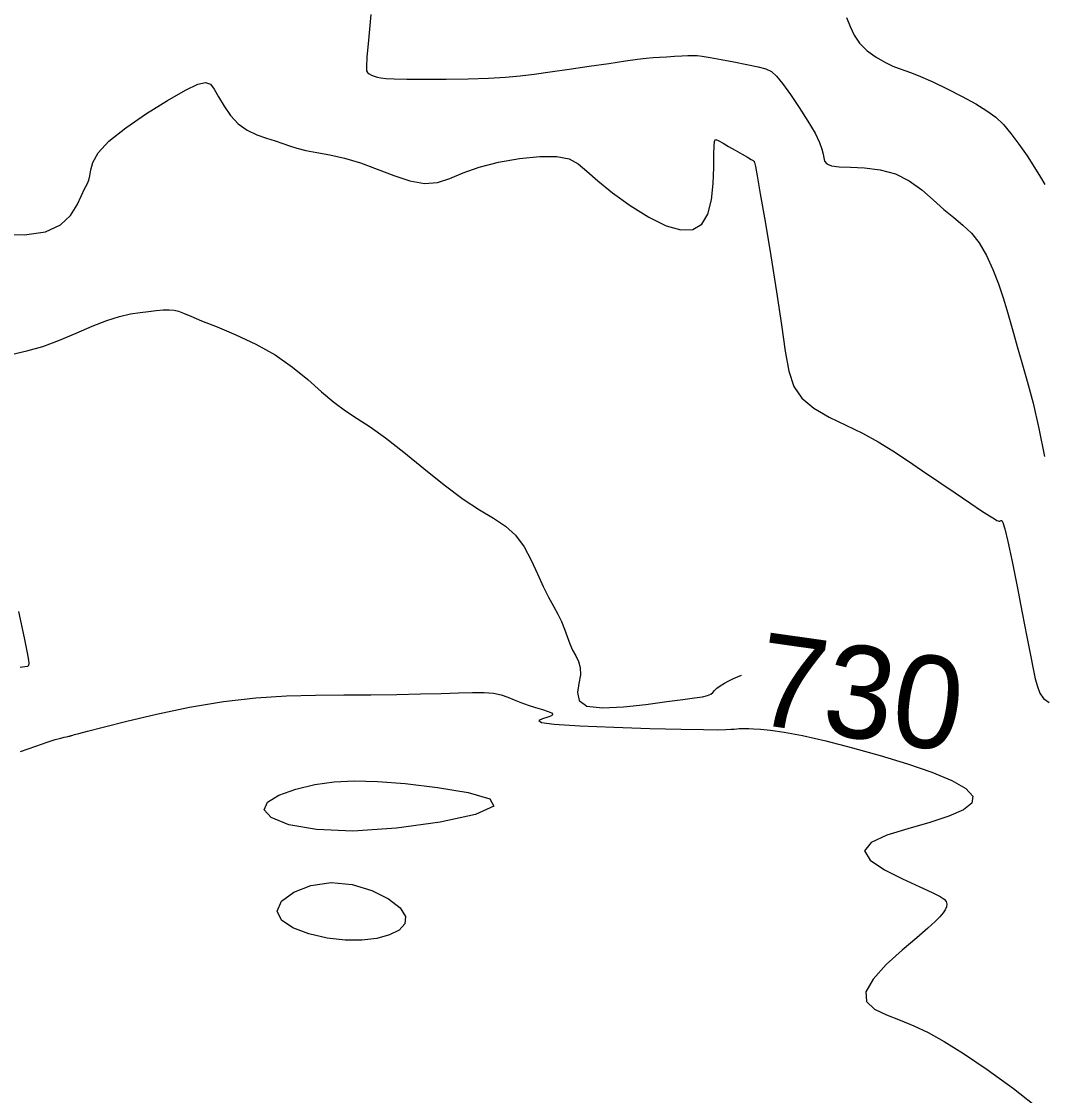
# Model space of a CAD drawing. Extents: x 2566142 to 2571431, y 418755 to 421584.
# Drawn here: x 2570497.9 to 2570718.9, y 419800.8 to 420033 of the extents above; entities that cross this region are included whole.
import ezdxf

# ---------------------------------------------------------------- set-up
doc = ezdxf.new("R2010")
doc.units = 0
for name, color, linetype in [('Contour_ADS_Label_Major', 7, 'Continuous'), ('Contour_ADS_Major', 7, 'Continuous'), ('Contour_ADS_Minor', 7, 'Continuous')]:
    doc.layers.add(name, color=color, linetype=linetype)

msp = doc.modelspace()

# ---------------------------------------------------------------- linework, layer by layer
at = {"layer": 'Contour_ADS_Major'}
for points in [[(2570495.67, 419961.05), (2570499.04, 419961.8), (2570502.51, 419962.8), (2570506.1, 419964.13), (2570509.69, 419965.64), (2570513.15, 419967.13), (2570516.31, 419968.4), (2570519.07, 419969.27), (2570521.46, 419969.82), (2570523.54, 419970.15), (2570525.38, 419970.36), (2570527.03, 419970.54), (2570528.5, 419970.67), (2570529.79, 419970.72), (2570530.89, 419970.65), (2570531.85, 419970.43), (2570532.94, 419970), (2570534.5, 419969.32), (2570536.84, 419968.33), (2570540.18, 419966.99), (2570544.22, 419965.3), (2570548.55, 419963.28), (2570552.75, 419960.94), (2570556.51, 419958.32), (2570559.81, 419955.6), (2570562.76, 419952.99), (2570565.44, 419950.71), (2570567.95, 419948.87), (2570570.5, 419947.21), (2570573.32, 419945.38), (2570576.63, 419943.02), (2570580.57, 419939.91), (2570584.89, 419936.37), (2570589.27, 419932.83), (2570593.37, 419929.76), (2570596.94, 419927.44), (2570599.98, 419925.63), (2570602.55, 419923.93), (2570604.72, 419921.97), (2570606.56, 419919.46), (2570608.13, 419916.57), (2570609.5, 419913.61), (2570610.72, 419910.87), (2570611.87, 419908.57), (2570612.92, 419906.64), (2570613.85, 419904.93)], [(2570497.57, 419893.47), (2570498.64, 419893.57), (2570499.23, 419893.69), (2570499.48, 419893.91), (2570499.53, 419894.26), (2570499.47, 419894.93), (2570499.2, 419896.53), (2570498.54, 419899.8), (2570497.32, 419905.45)], [(2570613.85, 419904.93), (2570614.66, 419903.32), (2570615.33, 419901.68), (2570615.91, 419900.06), (2570616.47, 419898.52), (2570617.07, 419897.11), (2570617.74, 419895.87), (2570618.35, 419894.67), (2570618.74, 419893.37), (2570618.77, 419891.82), (2570618.39, 419889.93), (2570618.1, 419887.95), (2570618.49, 419886.21), (2570620.18, 419885.03), (2570623.55, 419884.63), (2570628.06, 419884.84), (2570632.94, 419885.4), (2570637.43, 419886.01), (2570640.91, 419886.47), (2570643.42, 419886.8), (2570645.14, 419887.05), (2570646.26, 419887.31), (2570646.95, 419887.62), (2570647.4, 419887.99), (2570647.77, 419888.42), (2570648.26, 419888.91), (2570648.98, 419889.43), (2570649.89, 419889.97), (2570650.88, 419890.5), (2570651.86, 419890.98), (2570652.76, 419891.39), (2570653.58, 419891.7), (2570653.59, 419891.7)]]:
    msp.add_lwpolyline(points, dxfattribs=at)
at = {"layer": 'Contour_ADS_Minor'}
for points in [[(2570573.46, 420034.56), (2570572.94, 420028.98), (2570572.6, 420025.31), (2570572.46, 420023.29), (2570572.51, 420022.36), (2570572.73, 420021.98), (2570573.08, 420021.7), (2570573.56, 420021.44), (2570574.14, 420021.2), (2570574.8, 420020.99), (2570575.56, 420020.82), (2570576.68, 420020.7), (2570578.46, 420020.61), (2570581.22, 420020.56), (2570585.1, 420020.54), (2570589.71, 420020.56), (2570594.5, 420020.63), (2570598.91, 420020.76), (2570602.56, 420020.97), (2570605.71, 420021.26), (2570608.79, 420021.64), (2570612.22, 420022.14), (2570616.3, 420022.73), (2570620.68, 420023.37), (2570624.91, 420023.98), (2570628.51, 420024.49), (2570631.14, 420024.85), (2570633.01, 420025.07), (2570634.47, 420025.22), (2570635.85, 420025.32), (2570637.41, 420025.41), (2570639.08, 420025.5), (2570640.67, 420025.58), (2570642.02, 420025.64), (2570643.05, 420025.67), (2570643.98, 420025.64), (2570645.12, 420025.52), (2570646.79, 420025.25), (2570649.17, 420024.83), (2570651.96, 420024.31), (2570654.77, 420023.75), (2570657.17, 420023.24), (2570658.89, 420022.78), (2570660.12, 420022.19), (2570661.2, 420021.22), (2570662.48, 420019.63), (2570664.17, 420017.27), (2570666.09, 420014.43), (2570667.97, 420011.5), (2570669.5, 420008.89), (2570670.47, 420006.88), (2570670.99, 420005.42), (2570671.24, 420004.35), (2570671.37, 420003.54), (2570671.58, 420002.85), (2570672.07, 420002.28), (2570673.04, 420001.85), (2570674.71, 420001.6), (2570677.18, 420001.51), (2570680.23, 420001.38), (2570683.57, 420000.99), (2570686.87, 420000.1), (2570689.88, 419998.58), (2570692.61, 419996.61), (2570695.08, 419994.46), (2570697.37, 419992.41), (2570699.49, 419990.66), (2570701.47, 419989.03), (2570703.31, 419987.28), (2570705.01, 419985.15), (2570706.56, 419982.47), (2570707.96, 419979.42), (2570709.17, 419976.28), (2570710.19, 419973.29), (2570711, 419970.66), (2570711.7, 419968.19), (2570712.41, 419965.65), (2570713.22, 419962.77)], [(2570676.33, 420033.88), (2570677.08, 420031.94), (2570677.94, 420030.07), (2570679.13, 420028.31), (2570680.77, 420026.72), (2570682.69, 420025.34), (2570684.63, 420024.21), (2570686.36, 420023.38), (2570687.72, 420022.83), (2570688.93, 420022.42), (2570690.34, 420021.93), (2570692.28, 420021.16), (2570694.96, 420019.96), (2570698.1, 420018.46), (2570701.34, 420016.81), (2570704.29, 420015.21), (2570706.67, 420013.75), (2570708.58, 420012.32), (2570710.24, 420010.75), (2570711.87, 420008.85), (2570713.6, 420006.51), (2570715.36, 420003.96), (2570716.97, 420001.48)], [(2570493.41, 419987.08), (2570498.56, 419986.93), (2570503.04, 419987.54), (2570506.31, 419989.04), (2570508.5, 419991.12), (2570509.91, 419993.37), (2570510.84, 419995.38), (2570511.54, 419996.83), (2570512.08, 419997.86), (2570512.46, 419998.73), (2570512.69, 419999.68), (2570512.86, 420000.93), (2570513.32, 420002.57), (2570514.49, 420004.62), (2570516.79, 420007.13), (2570520.44, 420010.07), (2570524.91, 420013.14), (2570529.45, 420015.96), (2570533.33, 420018.17), (2570536, 420019.46), (2570537.68, 420019.86), (2570538.73, 420019.46), (2570539.57, 420018.37), (2570540.52, 420016.72), (2570541.68, 420014.75), (2570543.08, 420012.73), (2570544.75, 420010.92), (2570546.7, 420009.55), (2570548.79, 420008.55), (2570550.86, 420007.81), (2570552.76, 420007.21)], [(2570552.76, 420007.21), (2570554.38, 420006.66), (2570555.87, 420006.14), (2570557.46, 420005.64), (2570559.37, 420005.17), (2570561.75, 420004.72), (2570564.58, 420004.18), (2570567.76, 420003.46), (2570571.19, 420002.45), (2570574.79, 420001.12), (2570578.41, 419999.72), (2570581.88, 419998.57), (2570585.05, 419998), (2570587.84, 419998.24), (2570590.52, 419999.1), (2570593.41, 420000.3), (2570596.85, 420001.57), (2570601.04, 420002.65), (2570605.59, 420003.43), (2570609.97, 420003.85), (2570613.66, 420003.83), (2570616.3, 420003.31), (2570618.28, 420002.27), (2570620.16, 420000.7), (2570622.5, 419998.59), (2570625.71, 419996.01), (2570629.53, 419993.27), (2570633.53, 419990.76), (2570637.3, 419988.89), (2570640.49, 419987.98), (2570643.05, 419988.09), (2570644.99, 419989.22), (2570646.33, 419991.37), (2570647.11, 419994.46), (2570647.47, 419998.02), (2570647.58, 420001.5), (2570647.6, 420004.35), (2570647.67, 420006.17), (2570647.79, 420007.1), (2570647.92, 420007.45), (2570648.05, 420007.5), (2570648.17, 420007.48), (2570648.38, 420007.39), (2570648.81, 420007.17), (2570649.6, 420006.73), (2570650.81, 420006.04), (2570652.26, 420005.21), (2570653.72, 420004.38), (2570654.92, 420003.68), (2570655.7, 420003.22), (2570656.11, 420002.97), (2570656.28, 420002.86), (2570656.31, 420002.82), (2570656.32, 420002.8), (2570656.33, 420002.78), (2570656.35, 420002.74), (2570656.37, 420002.69), (2570656.43, 420002.51), (2570656.6, 420001.7), (2570656.97, 419999.66), (2570657.66, 419995.8), (2570658.7, 419989.78), (2570659.94, 419982.36), (2570661.2, 419974.57), (2570662.28, 419967.43), (2570663.06, 419961.75), (2570663.82, 419957.44), (2570664.88, 419954.15), (2570666.62, 419951.57), (2570669.24, 419949.41), (2570672.54, 419947.51), (2570676.17, 419945.75), (2570679.79, 419944.01), (2570683.15, 419942.19), (2570686.33, 419940.24), (2570689.48, 419938.16), (2570692.76, 419935.91), (2570696.27, 419933.51), (2570699.77, 419931.14), (2570702.96, 419928.99), (2570705.52, 419927.27), (2570707.25, 419926.13), (2570708.28, 419925.48), (2570708.82, 419925.17), (2570709.09, 419925.06), (2570709.29, 419925.03), (2570709.45, 419925.04), (2570709.6, 419925.08), (2570709.74, 419925.15), (2570709.9, 419925.16), (2570710.14, 419924.73), (2570710.54, 419923.38), (2570711.19, 419920.65), (2570712.11, 419916.29), (2570713.2, 419910.87), (2570714.32, 419905.19), (2570715.31, 419900.04), (2570716.08, 419896.04), (2570716.66, 419893.09), (2570717.13, 419890.91), (2570717.59, 419889.24)], [(2570716.97, 420001.48), (2570718.28, 419999.36), (2570719.18, 419997.8)], [(2570713.22, 419962.77), (2570714.23, 419959.33), (2570715.39, 419955.26), (2570716.64, 419950.52), (2570717.88, 419945.07), (2570719.14, 419938.98)], [(2570717.59, 419889.24), (2570718.12, 419887.85), (2570718.9, 419886.7), (2570720.1, 419885.8)], [(2570497.69, 419875.22), (2570500.97, 419876.37), (2570503.43, 419877.21), (2570505.19, 419877.78), (2570506.37, 419878.12), (2570507.12, 419878.32), (2570507.58, 419878.42), (2570507.89, 419878.47), (2570508.09, 419878.51), (2570508.23, 419878.53), (2570508.34, 419878.56), (2570508.46, 419878.6), (2570508.6, 419878.65), (2570508.78, 419878.71), (2570509.01, 419878.78), (2570509.38, 419878.89), (2570510.29, 419879.13), (2570512.18, 419879.61), (2570515.53, 419880.48), (2570520.63, 419881.77), (2570527.07, 419883.3), (2570534.24, 419884.81), (2570541.56, 419886.06), (2570548.55, 419886.84), (2570555.17, 419887.24), (2570561.48, 419887.39)], [(2570561.48, 419887.39), (2570567.57, 419887.44), (2570573.46, 419887.48), (2570579.03, 419887.56), (2570584.14, 419887.66), (2570588.62, 419887.77), (2570592.36, 419887.9), (2570595.43, 419887.98), (2570597.92, 419887.97), (2570599.94, 419887.81), (2570601.61, 419887.46), (2570603.06, 419886.97), (2570604.43, 419886.4), (2570605.86, 419885.81), (2570607.45, 419885.25), (2570609.07, 419884.75), (2570610.57, 419884.29), (2570611.76, 419883.89), (2570612.51, 419883.55), (2570612.76, 419883.23), (2570612.51, 419882.92), (2570611.74, 419882.61), (2570610.57, 419882.26), (2570609.79, 419881.89), (2570610.31, 419881.52), (2570613.08, 419881.15), (2570618.63, 419880.8), (2570625.98, 419880.48), (2570633.75, 419880.22), (2570640.58, 419880.04), (2570645.4, 419879.95), (2570648.44, 419879.93), (2570650.22, 419879.96), (2570651.27, 419880.02), (2570652.02, 419880.08), (2570652.62, 419880.13), (2570653.11, 419880.18), (2570653.52, 419880.21), (2570653.93, 419880.22), (2570654.44, 419880.22), (2570655.16, 419880.19), (2570656.21, 419880.15), (2570657.72, 419880.06), (2570659.86, 419879.85), (2570662.82, 419879.41), (2570666.77, 419878.65), (2570671.81, 419877.5), (2570677.57, 419876.03), (2570683.61, 419874.35), (2570689.48, 419872.55), (2570694.74, 419870.74), (2570699.06, 419868.95), (2570702.14, 419867.23), (2570703.66, 419865.59), (2570703.41, 419864.07), (2570701.58, 419862.63), (2570698.45, 419861.25), (2570694.33, 419859.9), (2570689.59, 419858.53), (2570685.05, 419857.1), (2570681.62, 419855.52), (2570680.22, 419853.74), (2570681.42, 419851.73), (2570684.51, 419849.64), (2570688.45, 419847.66), (2570692.17, 419845.98), (2570694.85, 419844.76), (2570696.53, 419843.9), (2570697.45, 419843.28), (2570697.88, 419842.76), (2570698.02, 419842.22), (2570697.94, 419841.64), (2570697.66, 419841.01), (2570697.19, 419840.31), (2570696.51, 419839.51), (2570695.47, 419838.47), (2570693.86, 419837), (2570691.49, 419834.96), (2570688.31, 419832.24), (2570684.91, 419829.14), (2570682.04, 419826.02), (2570680.45, 419823.27), (2570680.66, 419821.14), (2570682.34, 419819.54), (2570684.95, 419818.28), (2570687.93, 419817.14), (2570690.86, 419815.92), (2570693.93, 419814.45), (2570697.41, 419812.5), (2570701.63, 419809.9), (2570706.74, 419806.5), (2570712.43, 419802.4), (2570718.23, 419797.74)]]:
    msp.add_lwpolyline(points, dxfattribs=at)
for points in [[(2570561.33, 419868.05), (2570565.48, 419868.65), (2570569.86, 419868.87), (2570574.86, 419868.74), (2570580.84, 419868.27), (2570587.84, 419867.47), (2570594.51, 419866.37), (2570599.14, 419865), (2570600.02, 419863.39), (2570596.04, 419861.6), (2570588.42, 419859.91), (2570578.99, 419858.61), (2570569.56, 419858.02), (2570561.66, 419858.34), (2570555.73, 419859.39), (2570551.91, 419860.92), (2570550.35, 419862.63), (2570551.07, 419864.3), (2570553.57, 419865.81), (2570557.2, 419867.08), (2570561.33, 419868.05)], [(2570563.96, 419834.87), (2570560.04, 419835.78), (2570556.56, 419837.1), (2570554.08, 419838.77), (2570553.15, 419840.71), (2570554.14, 419842.83), (2570556.75, 419844.8), (2570560.49, 419846.28), (2570564.86, 419846.91), (2570569.39, 419846.46), (2570573.67, 419845.16), (2570577.27, 419843.35), (2570579.79, 419841.39), (2570580.93, 419839.56), (2570580.78, 419837.97), (2570579.57, 419836.62), (2570577.49, 419835.56), (2570574.75, 419834.82), (2570571.49, 419834.43), (2570567.85, 419834.43), (2570563.96, 419834.87)]]:
    msp.add_lwpolyline(points, close=True, dxfattribs=at)

# ---------------------------------------------------------------- texts
at = {"layer": 'Contour_ADS_Label_Major'}
msp.add_text('730', height=20, rotation=351.9209, dxfattribs=at).set_placement((2570655.76, 419881.29))

doc.saveas('drawing.dxf')
